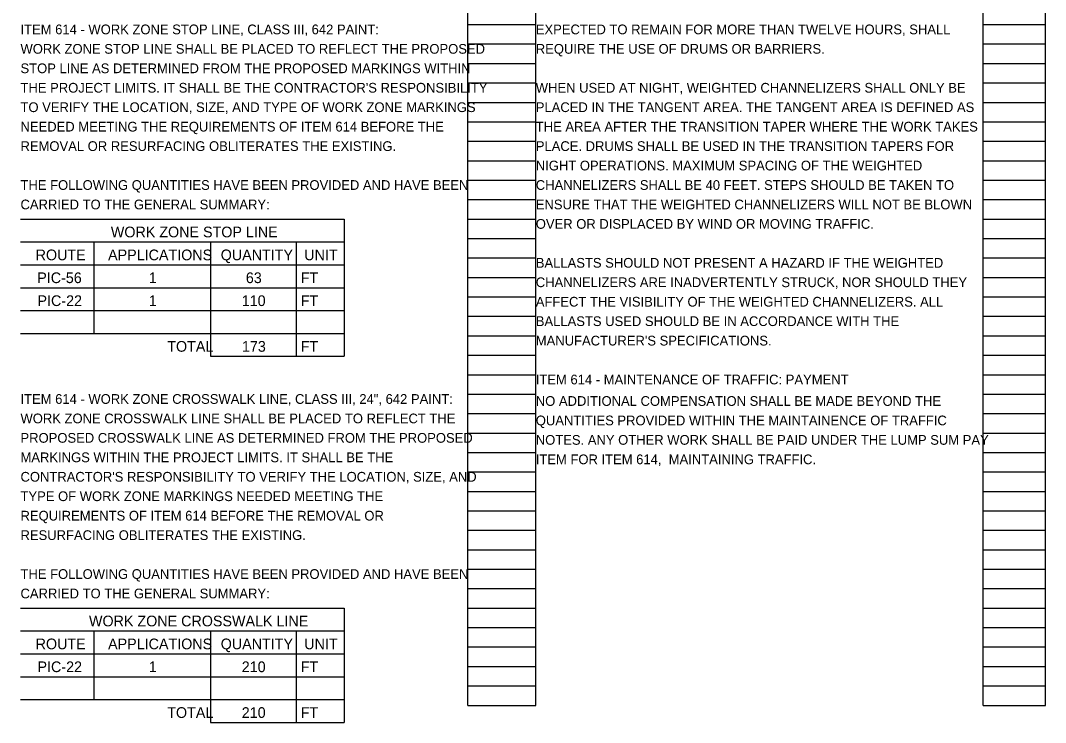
# Model space of a CAD drawing. Extents: x 24172 to 24226.9, y 11011.9 to 11091.2.
# Drawn here: x 24212.19 to 24226.95, y 11012.63 to 11022.73 of the extents above; entities that cross this region are included whole.
import ezdxf

# ---------------------------------------------------------------- set-up
doc = ezdxf.new("R2010")
doc.units = 0
doc.layers.add('SC_Scratch1', color=7, linetype='Continuous')
doc.layers.add('SH_Data', color=7, linetype='Continuous')

msp = doc.modelspace()

# ---------------------------------------------------------------- linework, layer by layer
at = {"layer": 'SH_Data'}
for p, q in [((24218.63, 11012.874), (24218.63, 11033.034)), ((24219.61, 11012.874), (24219.61, 11033.034)), ((24226.05, 11012.874), (24226.05, 11033.034)), ((24226.95, 11012.874), (24226.95, 11033.034)), ((24218.63, 11022.674), (24219.61, 11022.674)), ((24226.05, 11022.674), (24226.95, 11022.674)), ((24218.63, 11022.394), (24219.61, 11022.394)), ((24226.05, 11022.394), (24226.95, 11022.394)), ((24218.63, 11022.114), (24219.61, 11022.114)), ((24226.05, 11022.114), (24226.95, 11022.114)), ((24218.63, 11021.834), (24219.61, 11021.834)), ((24226.05, 11021.834), (24226.95, 11021.834)), ((24218.63, 11021.554), (24219.61, 11021.554)), ((24226.05, 11021.554), (24226.95, 11021.554)), ((24218.63, 11021.274), (24219.61, 11021.274)), ((24226.05, 11021.274), (24226.95, 11021.274)), ((24218.63, 11020.994), (24219.61, 11020.994)), ((24226.05, 11020.994), (24226.95, 11020.994)), ((24218.63, 11020.714), (24219.61, 11020.714)), ((24226.05, 11020.714), (24226.95, 11020.714)), ((24218.63, 11020.434), (24219.61, 11020.434)), ((24226.05, 11020.434), (24226.95, 11020.434)), ((24218.63, 11020.154), (24219.61, 11020.154)), ((24226.05, 11020.154), (24226.95, 11020.154)), ((24212.19, 11019.874), (24216.851, 11019.874)), ((24216.851, 11019.874), (24216.851, 11017.898)), ((24218.63, 11019.874), (24219.61, 11019.874)), ((24226.05, 11019.874), (24226.95, 11019.874)), ((24212.19, 11019.545), (24216.851, 11019.545)), ((24213.244, 11019.545), (24213.244, 11018.227)), ((24214.924, 11019.545), (24214.924, 11017.898)), ((24216.159, 11019.545), (24216.159, 11017.898)), ((24218.63, 11019.594), (24219.61, 11019.594)), ((24226.05, 11019.594), (24226.95, 11019.594)), ((24212.19, 11019.215), (24216.851, 11019.215)), ((24218.63, 11019.314), (24219.61, 11019.314)), ((24226.05, 11019.314), (24226.95, 11019.314)), ((24218.63, 11019.034), (24219.61, 11019.034)), ((24226.05, 11019.034), (24226.95, 11019.034)), ((24212.19, 11018.886), (24216.851, 11018.886)), ((24218.63, 11018.754), (24219.61, 11018.754)), ((24226.05, 11018.754), (24226.95, 11018.754)), ((24212.19, 11018.556), (24216.851, 11018.556)), ((24218.63, 11018.474), (24219.61, 11018.474)), ((24226.05, 11018.474), (24226.95, 11018.474)), ((24212.19, 11018.227), (24216.851, 11018.227)), ((24218.63, 11018.194), (24219.61, 11018.194)), ((24226.05, 11018.194), (24226.95, 11018.194)), ((24214.924, 11017.898), (24216.851, 11017.898)), ((24218.63, 11017.914), (24219.61, 11017.914)), ((24226.05, 11017.914), (24226.95, 11017.914)), ((24218.63, 11017.634), (24219.61, 11017.634)), ((24226.05, 11017.634), (24226.95, 11017.634)), ((24218.63, 11017.354), (24219.61, 11017.354)), ((24226.05, 11017.354), (24226.95, 11017.354)), ((24218.63, 11017.074), (24219.61, 11017.074)), ((24226.05, 11017.074), (24226.95, 11017.074)), ((24218.63, 11016.794), (24219.61, 11016.794)), ((24226.05, 11016.794), (24226.95, 11016.794)), ((24218.63, 11016.514), (24219.61, 11016.514)), ((24226.05, 11016.514), (24226.95, 11016.514)), ((24218.63, 11016.234), (24219.61, 11016.234)), ((24226.05, 11016.234), (24226.95, 11016.234)), ((24218.63, 11015.954), (24219.61, 11015.954)), ((24226.05, 11015.954), (24226.95, 11015.954)), ((24218.63, 11015.674), (24219.61, 11015.674)), ((24226.05, 11015.674), (24226.95, 11015.674)), ((24218.63, 11015.394), (24219.61, 11015.394)), ((24226.05, 11015.394), (24226.95, 11015.394)), ((24218.63, 11015.114), (24219.61, 11015.114)), ((24226.05, 11015.114), (24226.95, 11015.114)), ((24218.63, 11014.834), (24219.61, 11014.834)), ((24226.05, 11014.834), (24226.95, 11014.834)), ((24218.63, 11014.554), (24219.61, 11014.554)), ((24226.05, 11014.554), (24226.95, 11014.554)), ((24212.19, 11014.274), (24216.851, 11014.274)), ((24216.851, 11014.274), (24216.851, 11012.627)), ((24218.63, 11014.274), (24219.61, 11014.274)), ((24226.05, 11014.274), (24226.95, 11014.274)), ((24212.19, 11013.945), (24216.851, 11013.945)), ((24213.244, 11013.945), (24213.244, 11012.956)), ((24214.924, 11013.945), (24214.924, 11012.627)), ((24216.159, 11013.945), (24216.159, 11012.627)), ((24218.63, 11013.994), (24219.61, 11013.994)), ((24226.05, 11013.994), (24226.95, 11013.994)), ((24212.19, 11013.615), (24216.851, 11013.615)), ((24218.63, 11013.714), (24219.61, 11013.714)), ((24226.05, 11013.714), (24226.95, 11013.714)), ((24218.63, 11013.434), (24219.61, 11013.434)), ((24226.05, 11013.434), (24226.95, 11013.434)), ((24212.19, 11013.286), (24216.851, 11013.286)), ((24218.63, 11013.154), (24219.61, 11013.154)), ((24226.05, 11013.154), (24226.95, 11013.154)), ((24212.19, 11012.956), (24216.851, 11012.956)), ((24218.63, 11012.874), (24219.61, 11012.874)), ((24226.05, 11012.874), (24226.95, 11012.874)), ((24214.924, 11012.627), (24216.851, 11012.627))]:
    msp.add_line(p, q, dxfattribs=at)

# ---------------------------------------------------------------- texts
at = {"layer": 'SC_Scratch1'}
for s, p in [('ITEM 614 - WORK ZONE STOP LINE, CLASS III, 642 PAINT:', (24212.19, 11022.534)), ('EXPECTED TO REMAIN FOR MORE THAN TWELVE HOURS, SHALL ', (24219.61, 11022.534)), ('WORK ZONE STOP LINE SHALL BE PLACED TO REFLECT THE PROPOSED ', (24212.19, 11022.254)), ('REQUIRE THE USE OF DRUMS OR BARRIERS.', (24219.61, 11022.254)), ('STOP LINE AS DETERMINED FROM THE PROPOSED MARKINGS WITHIN ', (24212.19, 11021.974)), ("THE PROJECT LIMITS. IT SHALL BE THE CONTRACTOR'S RESPONSIBILITY ", (24212.19, 11021.694)), ('WHEN USED AT NIGHT, WEIGHTED CHANNELIZERS SHALL ONLY BE ', (24219.61, 11021.694)), ('TO VERIFY THE LOCATION, SIZE, AND TYPE OF WORK ZONE MARKINGS ', (24212.19, 11021.414)), ('PLACED IN THE TANGENT AREA. THE TANGENT AREA IS DEFINED AS ', (24219.61, 11021.414)), ('NEEDED MEETING THE REQUIREMENTS OF ITEM 614 BEFORE THE ', (24212.19, 11021.134)), ('THE AREA AFTER THE TRANSITION TAPER WHERE THE WORK TAKES ', (24219.61, 11021.134)), ('REMOVAL OR RESURFACING OBLITERATES THE EXISTING.', (24212.19, 11020.854)), ('PLACE. DRUMS SHALL BE USED IN THE TRANSITION TAPERS FOR ', (24219.61, 11020.854)), ('NIGHT OPERATIONS. MAXIMUM SPACING OF THE WEIGHTED ', (24219.61, 11020.574)), ('THE FOLLOWING QUANTITIES HAVE BEEN PROVIDED AND HAVE BEEN ', (24212.19, 11020.294)), ('CHANNELIZERS SHALL BE 40 FEET. STEPS SHOULD BE TAKEN TO ', (24219.61, 11020.294)), ('CARRIED TO THE GENERAL SUMMARY:', (24212.19, 11020.014)), ('ENSURE THAT THE WEIGHTED CHANNELIZERS WILL NOT BE BLOWN ', (24219.61, 11020.014)), ('OVER OR DISPLACED BY WIND OR MOVING TRAFFIC.', (24219.61, 11019.734)), ('BALLASTS SHOULD NOT PRESENT A HAZARD IF THE WEIGHTED ', (24219.61, 11019.174)), ('CHANNELIZERS ARE INADVERTENTLY STRUCK, NOR SHOULD THEY ', (24219.61, 11018.894)), ('AFFECT THE VISIBILITY OF THE WEIGHTED CHANNELIZERS. ALL ', (24219.61, 11018.614)), ('BALLASTS USED SHOULD BE IN ACCORDANCE WITH THE ', (24219.61, 11018.334)), ("MANUFACTURER'S SPECIFICATIONS.", (24219.61, 11018.054)), ('ITEM 614 - MAINTENANCE OF TRAFFIC: PAYMENT', (24219.61, 11017.494)), ('ITEM 614 - WORK ZONE CROSSWALK LINE, CLASS III, 24", 642 PAINT:', (24212.19, 11017.214)), ('NO ADDITIONAL COMPENSATION SHALL BE MADE BEYOND THE ', (24219.61, 11017.185)), ('WORK ZONE CROSSWALK LINE SHALL BE PLACED TO REFLECT THE ', (24212.19, 11016.934)), ('QUANTITIES PROVIDED WITHIN THE MAINTAINENCE OF TRAFFIC ', (24219.61, 11016.905)), ('PROPOSED CROSSWALK LINE AS DETERMINED FROM THE PROPOSED ', (24212.19, 11016.654)), ('NOTES. ANY OTHER WORK SHALL BE PAID UNDER THE LUMP SUM PAY ', (24219.61, 11016.625)), ('MARKINGS WITHIN THE PROJECT LIMITS. IT SHALL BE THE ', (24212.19, 11016.374)), ('ITEM FOR ITEM 614,  MAINTAINING TRAFFIC.', (24219.61, 11016.345)), ("CONTRACTOR'S RESPONSIBILITY TO VERIFY THE LOCATION, SIZE, AND ", (24212.19, 11016.094)), ('TYPE OF WORK ZONE MARKINGS NEEDED MEETING THE ', (24212.19, 11015.814)), ('REQUIREMENTS OF ITEM 614 BEFORE THE REMOVAL OR ', (24212.19, 11015.534)), ('RESURFACING OBLITERATES THE EXISTING.', (24212.19, 11015.254)), ('THE FOLLOWING QUANTITIES HAVE BEEN PROVIDED AND HAVE BEEN ', (24212.19, 11014.694)), ('CARRIED TO THE GENERAL SUMMARY:', (24212.19, 11014.414))]:
    msp.add_text(s, height=0.14, dxfattribs=at).set_placement(p)
at = {"layer": 'SH_Data'}
for s, p in [('WORK ZONE STOP LINE', (24213.491, 11019.611)), ('ROUTE', (24212.408, 11019.281)), ('APPLICATIONS', (24213.451, 11019.281)), ('QUANTITY', (24215.073, 11019.281)), ('UNIT', (24216.276, 11019.281)), ('PIC-56', (24212.431, 11018.952)), ('1', (24214.038, 11018.952)), ('63', (24215.435, 11018.952)), ('FT', (24216.225, 11018.952)), ('PIC-22', (24212.435, 11018.622)), ('1', (24214.038, 11018.622)), ('110', (24215.376, 11018.622)), ('FT', (24216.225, 11018.622)), ('TOTAL', (24214.303, 11017.964)), ('173', (24215.379, 11017.964)), ('FT', (24216.225, 11017.964)), ('WORK ZONE CROSSWALK LINE', (24213.176, 11014.011)), ('ROUTE', (24212.408, 11013.681)), ('APPLICATIONS', (24213.451, 11013.681)), ('QUANTITY', (24215.073, 11013.681)), ('UNIT', (24216.276, 11013.681)), ('PIC-22', (24212.435, 11013.352)), ('1', (24214.038, 11013.352)), ('210', (24215.376, 11013.352)), ('FT', (24216.225, 11013.352)), ('TOTAL', (24214.303, 11012.693)), ('210', (24215.376, 11012.693)), ('FT', (24216.225, 11012.693))]:
    msp.add_text(s, height=0.154, dxfattribs=at).set_placement(p)

doc.saveas('drawing.dxf')
